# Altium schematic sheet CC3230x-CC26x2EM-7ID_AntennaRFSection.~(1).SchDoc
size 558 x 431 mm; Date: Not shown in title block; ApprovedBy: Not shown in title block; CheckedBy: Not shown in title block; Author: Not shown in title block; CompanyName: Not shown in title block; Engineer: Not shown in title block; Organization: Not shown in title block; Address1: Not shown in title block; Address2: Not shown in title block; Address3: Not shown in title block; Address4: Not shown in title block; DocumentNumber: 4; Revision: Use project parameter SCH_Rev; SheetNumber: 4; SheetTotal: 5; PageSetup: Record=PageOptions¦CenterHorizontal=True¦CenterVertical=True¦PrintScale=1.00¦XCorrection=1.00¦YCorrection=1.00¦PrintKind=0¦BorderSize=5000000¦LeftOffset=0¦BottomOffset=0¦Orientation=2¦PaperLength=1000¦PaperWidth=1000¦Scale=100¦PaperSource=15¦PrintQuality=600¦MediaType=1¦DitherType=10¦PaperKind=Letter¦PrintScaleMode=1
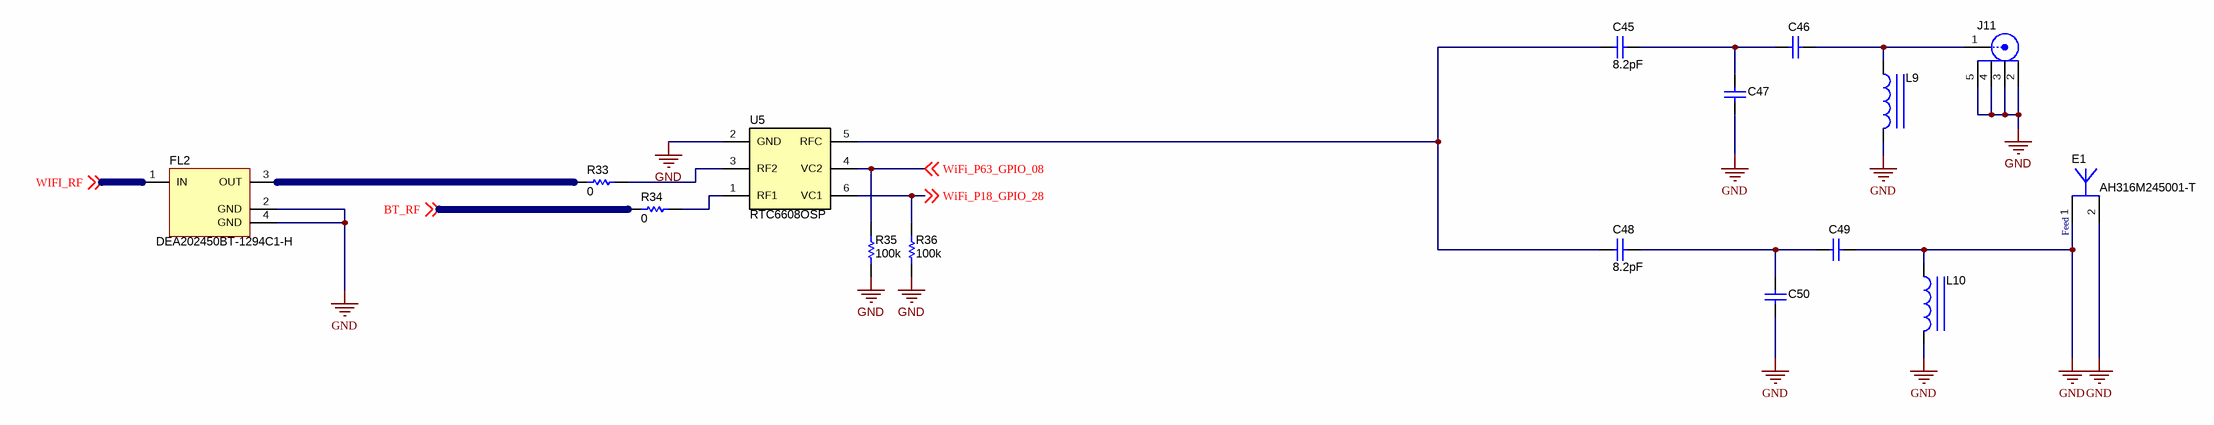
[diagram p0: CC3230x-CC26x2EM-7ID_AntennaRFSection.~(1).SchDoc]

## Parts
C45  ValueDisplayed: 8.2pF  [0402S]  (hidden comment: CMP-0006495-2)
C46  CMP-0006447-2  [0402L]  (value not drawn)
C47  CMP-0006426-2  [0402S]  (value not drawn)
C48  ValueDisplayed: 8.2pF  [0402S]  (hidden comment: CMP-0006495-2)
C49  CMP-0006447-2  [0402L]  (value not drawn)
C50  CMP-0006426-2  [0402S]  (value not drawn)
E1  AH316M245001-T  [TAYO_AH316M]
FL2  PartNumber: DEA202450BT-1294C1-H  [TDK_DEA202450BT-1294C1-H]  (hidden comment: CMP-0002039-2)
J11  CMP-0055832-1  [Hustsan_SMA-10V21-TGG]  (value not drawn)
L9  LQG15HS3N9S02D  [IND_LQG15H]  (value not drawn)
L10  LQG15HS3N9S02D  [IND_LQG15H]  (value not drawn)
R33  ValueDisplayed: 0  [0201]  (hidden comment: ERJ-1GE0R00C)
R34  ValueDisplayed: 0  [0201]  (hidden comment: ERJ-1GE0R00C)
R35  ValueDisplayed: 100k  [0201]  (hidden comment: RC0201JR-7D100KL)
R36  ValueDisplayed: 100k  [0201]  (hidden comment: RC0201JR-7D100KL)
U5  RTC6608OSP  [Richwave_RTC6608OSP]

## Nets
GND: C47.2 C49.2 C50.2 E1.1 E1.2 FL2.2(GND) FL2.4(GND) J11.2 J11.3 J11.4 J11.5 L9.2 L10.1 L10.2 R35.1 R36.1 U5.2(GND)
BT_RF: R34.2 ; off-sheet BT_RF
WiFi_P18_GPIO_28: R36.2 U5.6(VC1) ; off-sheet WiFi_P18_GPIO_28
WiFi_P63_GPIO_08: R35.2 U5.4(VC2) ; off-sheet WiFi_P63_GPIO_08
WIFI_RF: FL2.1(IN) ; off-sheet WIFI_RF
NetC45_1: C45.1 C48.1 U5.5(RFC)
NetC45_2: C45.2 C46.1 C47.1
NetC46_2: C46.2 J11.1 L9.1
NetC48_2: C48.2 C49.1 C50.1
NetFL2_3: FL2.3(OUT) R33.2
NetR33_1: R33.1 U5.3(RF2)
NetR34_1: R34.1 U5.1(RF1)

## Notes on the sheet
- (near E1) Feed

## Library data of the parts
C45 C48 = CMP-0006495-2: CAP, CERM, 8.2 pF, 50 V, +/- 5%, C0G/NP0, 0402; PartNumber: GRM1555C1H8R2CA01D; Manufacturer: MuRata; Alternate PartNumber: 0402N8R2C500CT; Alternate Manufacturer: Walsin; Polarized: N; CompType: Capacitor; Value: 8.2pF; U/M: EA; Value1: Unknown; VDC_V: 50V; TaMin_C: -55°C; TaMax_C: 125°C; Cap_Case: 0402; SizeArea_mm2: 0.5; SizeAreaWB_mm2: 3; SizeX_mm: 1; SizeZ_mm: 0.6; AEC Category: Q200
C46 C49 = CMP-0006447-2: CAP, CERM, 2.2 pF, 50 V, +/- 5%, C0G/NP0, 0402; PartNumber: GRM1555C1H2R2BA01D; Manufacturer: MuRata; Alternate PartNumber: ----; Polarized: N; CompType: Capacitor; Value: 2.2pF; U/M: EA; Value1: Unknown; VDC_V: 50V; TaMin_C: -55°C; TaMax_C: 125°C; Cap_Case: 0402; SizeArea_mm2: 0.5; SizeAreaWB_mm2: 3; SizeX_mm: 1; SizeZ_mm: 0.6; AEC Category: Q200
C47 C50 = CMP-0006426-2: CAP, CERM, 1 pF, 50 V, +/- 10%, C0G/NP0, 0402; PartNumber: GRM1555C1H1R0BA01D; Manufacturer: MuRata; Alternate PartNumber: ----; Polarized: N; CompType: Capacitor; Value: 1pF; U/M: EA; Value1: Unknown; VDC_V: 50V; TaMin_C: -55°C; TaMax_C: 125°C; Cap_Case: 0402; SizeAreaWB_mm2: 3; SizeZ_mm: 0.6; SizeX_mm: 1; SizeY_mm: 0.5; AEC Category: Q200
E1 = CMP-0002031-2: ANT BLUETOOTH W-LAN ZIGBEE WIMAX, SMD; Manufacturer: Taiyo Yuden; CompType: Antenna
FL2 = CMP-0002039-2: Multilayer Chip Band Pass Filter For 2.4GHz W-LAN/Bluetooth, SMD; Manufacturer: TDK; Alternate Manufacturer: ----; Value: 1.02 dB
J11 = CMP-0055832-1: Connector, SMA, Vertical, Gold, SMT; PartNumber: SMA-10V21-TGG; Manufacturer: Hus-Tsan Group Co., Ltd.; Alternate Manufacturer: 傲创; Alternate PartNumber: SMA-050710; CT: TRUE; CNHeader: FALSE
L9 L10 = CMP-0058633-2: Inductor, Multilayer, Air Core, 3.9 nH, 0.75 A, 0.14 ohm, SMD; Manufacturer: MuRata; Irms: 0.75A @ 25C rise; Green_Lifecycle: Active; SizeAreaWB_mm2: 3; DCR_ohm: 1.4d; Green_REACh: Passed; Value: 3.9nH; Imax_A: 7.5dA; SizeZ_mm: 0.55; SizeX_mm: 1; SizeY_mm: 0.5; Value2: 0.75A; AEC Qualified: N; AEC Category: Q200
R33 R34 = CMP-0027011-3: RES, 0, 5%, 0.05 W, 0201; Manufacturer: Panasonic; Alternate Manufacturer: Vishay-Dale; Alternate PartNumber: CRCW02010000Z0ED; CompType: Resistor; Value: 0; Value_Code: 0000; Power_W: 50mW; Value2: 0.05W; VDC_V: 15V; TempCo: 600 ppm/C; SizeArea_mm2: 0.18; SizeX_mm: 0.6; SizeY_mm: 0.3; SizeZ_mm: 0.26; EIA_Code: E24; U/M: EA; AEC Category: Q200
R35 R36 = CMP-0027184-1: RES, 100 k, 5%, 0.05 W, 0201; Manufacturer: Yageo America; Power_W: 50mW; TempCo: 200 ppm/C; U/M: EA; Value: 100k; EIA_Code: E24; SizeX_mm: 0.6; SizeY_mm: 0.3; SizeZ_mm: 0.26; Value2: 0.05W; SizeArea_mm2: 0.18; CompType: Resistor; AEC Qualified: N; VDC_V: 25V; AEC Category: Q200
U5 = CMP-0065464-1: 0.03 GHz-6 GHz SPDT Switch; Manufacturer: Richwave; Alternate Manufacturer: ----; SizeAreaWB_mm2: 4.0; SizeArea_mm2: 1.0; SizeZ_mm: 0.4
